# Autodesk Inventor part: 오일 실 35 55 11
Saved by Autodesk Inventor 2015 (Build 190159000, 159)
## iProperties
Created: 2025-06
Part Number: 오일 실 35 55 11
Material: 일반
Document SubType Name: Modeling
Designer: 104
Density: 1 g/cm^3
Appearance: 기본값
Author: 104
Author: jhkim
Description: 오일 실 - 비스프링, 조립 GA
Creation Date: 2025-05-23
Sending System: Autodesk Inventor 2026
Preprocessor: ST-DEVELOPER v20.1
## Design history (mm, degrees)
node "오일 실 35 55 111"
body "Solid1"
node "기준1"
